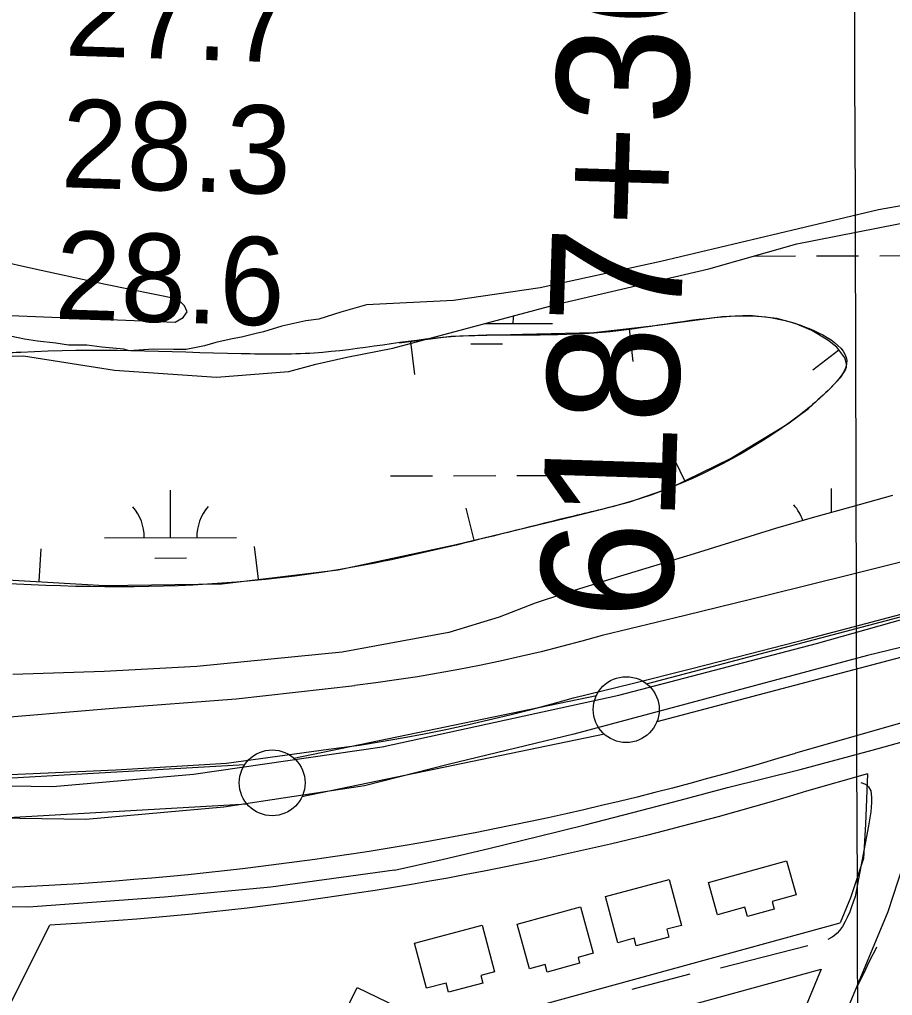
# Model space of a CAD drawing. Extents: x 3361039 to 3398939, y 576572 to 602007.
# Drawn here: x 3385593 to 3386256, y 584866 to 585607 of the extents above; entities that cross this region are included whole.
import ezdxf

# ---------------------------------------------------------------- set-up
doc = ezdxf.new("R2010")
doc.units = 0
for name, color, linetype in [('V-BLDG-OTLN', 7, 'Continuous'), ('V-BORW-LINE', 7, 'Continuous'), ('V-FLOD-BASE', 7, 'Continuous'), ('V-GRID-MAJR', 7, 'Continuous'), ('V-LEVE-TOET', 7, 'Continuous'), ('V-RIVR-RANG', 7, 'Continuous'), ('V-ROAD-CNTR', 7, 'Continuous'), ('V-SITE-VEGE', 7, 'Continuous'), ('V-SURV-IDEN', 7, 'Continuous'), ('V-SURV-LINE', 7, 'Continuous'), ('V-TOPO-MAJR', 7, 'Continuous'), ('V-TOPO-SHOR', 7, 'Continuous'), ('V-WETL-SWMP', 7, 'Continuous')]:
    doc.layers.add(name, color=color, linetype=linetype)

msp = doc.modelspace()

# ---------------------------------------------------------------- linework, layer by layer
at = {"layer": 'V-BLDG-OTLN'}
for points in [[(3386116.51, 584951.84), (3386175.84, 584968.41), (3386183.05, 584942.59), (3386164.78, 584937.48), (3386166.4, 584931.66), (3386146.19, 584926.01), (3386144.21, 584933.11), (3386123.37, 584927.29)], [(3386038.21, 584941.24), (3386086.54, 584954.2), (3386095.91, 584919.25), (3386084.9, 584916.3), (3386086.48, 584910.43), (3386061.7, 584903.79), (3386060.17, 584909.5), (3386047.62, 584906.15)], [(3385971.18, 584920.19), (3386019.31, 584933.36), (3386028.96, 584898.09), (3386017.46, 584894.95), (3386018.64, 584890.64), (3385993.94, 584883.88), (3385992.4, 584889.49), (3385980.48, 584886.23)], [(3385893.26, 584905.87), (3385944.69, 584919.43), (3385954, 584884.08), (3385943.67, 584881.36), (3385945.23, 584875.46), (3385919.06, 584868.56), (3385917.24, 584875.46), (3385902.3, 584871.53)], [(3385826.87, 584825.45), (3385849.68, 584872.18), (3385880.09, 584857.34), (3385874.59, 584846.08), (3385881.6, 584842.67), (3385869.64, 584818.17), (3385863.21, 584821.3), (3385857.85, 584810.33)]]:
    msp.add_lwpolyline(points, close=True, dxfattribs=at)
at = {"layer": 'V-BORW-LINE'}
for p, q in [((3386056.25, 585372.28), (3386059.14, 585347.45)), ((3385890.13, 585362.41), (3385893.34, 585337.62)), ((3386215.54, 585356.09), (3386195.69, 585340.89)), ((3386098.55, 585256.87), (3386087.53, 585279.31)), ((3385938.51, 585211.74), (3385932.63, 585236.04)), ((3385608.44, 585180.3), (3385609.88, 585205.26)), ((3385774.75, 585182.05), (3385771.8, 585206.88))]:
    msp.add_line(p, q, dxfattribs=at)
for points in [[(3385479.9, 585187.69), (3385658.02, 585177.45), (3385747.01, 585178.74), (3385835.24, 585189.26), (3385925.04, 585208.48), (3386014.23, 585230.05), (3386035.51, 585235.28), (3386056.71, 585240.88), (3386088.19, 585251.79), (3386133.12, 585273.84), (3386176.62, 585300.03), (3386192.55, 585311.85), (3386207.38, 585325.51), (3386216.96, 585335.43), (3386220.36, 585340.66), (3386221.23, 585343.19), (3386221.37, 585345.61), (3386219.95, 585350.33), (3386213.89, 585358.25), (3386207.13, 585363.73), (3386194.99, 585370.87), (3386182.35, 585376.31), (3386168.45, 585380.18), (3386147.58, 585382.28), (3386126.76, 585381.36), (3386078.16, 585374.83), (3386029.51, 585369.17), (3385975.3, 585367.99), (3385921.06, 585366.42), (3385881.61, 585361.31)], [(3385594.06, 585354.57), (3385547.09, 585351.02), (3385499.8, 585346.62), (3385437.72, 585344.58), (3385375.62, 585344.42), (3385247.69, 585348.26)]]:
    msp.add_lwpolyline(points, dxfattribs=at)
msp.add_spline([(3382571.75, 585529.85), (3382288.5, 585546.28), (3382119.28, 585556.22), (3382064.39, 585562.69), (3382006.96, 585576.93), (3381796, 585575.03), (3381691.54, 585581.2), (3381638.45, 585584.98), (3381607.38, 585576.47), (3381598.51, 585566.36), (3381610.08, 585526.4), (3381641.99, 585457.34), (3381686.19, 585430.69), (3381748.69, 585412.56), (3381952.89, 585396.92), (3382011.65, 585399.05), (3382060.7, 585404.53), (3382233.38, 585410.22), (3382597.39, 585393.13), (3382822.43, 585377.96), (3382985.12, 585375.03), (3383040.48, 585369.32), (3383111.3, 585349.64), (3383186.01, 585343.18), (3383349.37, 585344.09), (3383670.1, 585328.99), (3383776.96, 585325.83), (3383950.1, 585282.41), (3384048.66, 585281.9), (3384105.28, 585326.49), (3384120.75, 585332.34), (3384160.48, 585298.98), (3384209.82, 585275.27), (3384267.65, 585259.58), (3384373.27, 585255.57), (3384419.94, 585258.58), (3384709.73, 585239.38), (3384826.34, 585210.62), (3384946.51, 585203.35), (3385109.52, 585215.5), (3385207.25, 585213.25), (3385246.28, 585211.98), (3385305.12, 585207.81), (3385479.9, 585187.69), (3385835.24, 585189.26), (3386014.23, 585230.05), (3386056.71, 585240.88), (3386176.62, 585300.03), (3386207.38, 585325.51), (3386221.37, 585345.61), (3386182.35, 585376.31), (3386126.76, 585381.36), (3386029.51, 585369.17), (3385921.06, 585366.42), (3385817.08, 585354.08), (3385761.67, 585353.52), (3385594.41, 585354.59), (3385499.8, 585346.62), (3385375.62, 585344.42), (3385091.32, 585358.84), (3384912.21, 585381.83), (3384861.67, 585385.98), (3384294.69, 585385.71), (3384190.67, 585395.62), (3384128.27, 585377.4), (3384079.07, 585402.54), (3383956.19, 585439.51), (3383615.98, 585443.36), (3383292.93, 585470.42), (3383014.82, 585493.71), (3382867.4, 585507.63), (3382640.11, 585523.01), (3382571.75, 585529.85)], degree=3, dxfattribs=at)
at = {"layer": 'V-FLOD-BASE'}
for points in [[(3385851.46, 585056.16), (3385867.89, 585058.81), (3385884.3, 585061.67), (3385900.66, 585064.74), (3385916.99, 585068.03), (3385933.27, 585071.53), (3385949.51, 585075.24), (3385965.7, 585079.16), (3385981.84, 585083.29), (3385997.92, 585087.62), (3386013.94, 585092.17), (3386058.45, 585103), (3386102.89, 585114.06), (3386147.28, 585125.35), (3386191.62, 585136.87), (3386235.89, 585148.62), (3386506.81, 585220.01)], [(3384347.67, 585099.36), (3384436.64, 585093.72), (3384537.8, 585087.98), (3384639.32, 585081.53), (3384748.75, 585076.82), (3384851.34, 585069.99), (3384975.09, 585060.51), (3385074.47, 585056.23), (3385177.44, 585051.56), (3385286.49, 585043.97), (3385389.43, 585035.72), (3385466.57, 585032.3), (3385569.21, 585033.02), (3385666.5, 585037.36), (3385750.52, 585042.52), (3385828.11, 585053.1), (3385851.46, 585056.16)]]:
    msp.add_lwpolyline(points, dxfattribs=at)
at = {"layer": 'V-GRID-MAJR'}
msp.add_spline([(3386238.02, 582015.2), (3386220.4, 588073.24), (3386202.77, 594134.37), (3386185.13, 600195.51), (3386185.12, 600198.58)], degree=3, dxfattribs=at)
at = {"layer": 'V-LEVE-TOET'}
for points in [[(3386287.96, 585201.41), (3386224.97, 585185.6), (3386161.93, 585169.99), (3386098.84, 585154.57), (3386035.71, 585139.36), (3386020.32, 585135.07), (3386004.88, 585130.98), (3385989.39, 585127.09), (3385973.85, 585123.41), (3385958.26, 585119.94), (3385942.62, 585116.67), (3385926.94, 585113.61), (3385911.23, 585110.76), (3385895.47, 585108.11), (3385879.69, 585105.67), (3385863.87, 585103.44), (3385848.03, 585101.42)], [(3384277.82, 585153.03), (3384414.15, 585145.09), (3384554.88, 585132.69), (3384689.94, 585126.67), (3384819.93, 585119.41), (3384957.48, 585105.76), (3385126.78, 585097.6), (3385249.16, 585091.67), (3385351.25, 585085.24), (3385449.51, 585076.94), (3385561.77, 585075.52), (3385664.59, 585084.32), (3385757.88, 585091.27), (3385848.03, 585101.42)], [(3385878.15, 584961.12), (3385914.41, 584969.37), (3385950.64, 584977.93), (3385986.82, 584986.7), (3386022.95, 584995.68), (3386059.02, 585004.88), (3386095.04, 585014.29), (3386131.01, 585023.91), (3386158.53, 585030.71), (3386186, 585037.71), (3386213.42, 585044.91), (3386240.78, 585052.3), (3386268.1, 585059.89)], [(3385878.15, 584961.12), (3385784.16, 584948.37), (3385703.55, 584940.68), (3385600.1, 584933.16), (3385499.25, 584933.87), (3385340.74, 584943.86), (3385151.77, 584952.17), (3385022.42, 584959.42), (3384849.3, 584965.7), (3384655.92, 584978.48), (3384445.45, 584995.81), (3384273.63, 585007.16)]]:
    msp.add_lwpolyline(points, dxfattribs=at)
at = {"layer": 'V-ROAD-CNTR'}
for points in [[(3386593.92, 585167.42), (3386182.59, 585049.94)], [(3386182.39, 585049.88), (3386169.09, 585045.88), (3386155.81, 585041.97), (3386142.51, 585038.14), (3386129.18, 585034.39), (3386115.83, 585030.71), (3386102.46, 585027.1), (3386089.07, 585023.58), (3386075.66, 585020.13), (3386062.24, 585016.76), (3386048.79, 585013.46), (3386035.32, 585010.24), (3386021.84, 585007.11), (3386008.33, 585004.04), (3385994.81, 585001.06), (3385981.28, 584998.15), (3385967.72, 584995.32), (3385954.15, 584992.57), (3385940.57, 584989.9), (3385926.97, 584987.3), (3385913.35, 584984.78), (3385899.73, 584982.34), (3385886.08, 584979.98), (3385872.43, 584977.7), (3385858.76, 584975.5), (3385845.08, 584973.37), (3385831.38, 584971.32), (3385817.68, 584969.36), (3385803.96, 584967.47), (3385790.23, 584965.66), (3385776.5, 584963.92), (3385762.75, 584962.27), (3385748.99, 584960.7), (3385735.23, 584959.2), (3385721.46, 584957.79), (3385707.67, 584956.45), (3385693.89, 584955.19), (3385680.09, 584954.01), (3385666.29, 584952.91), (3385652.48, 584951.89), (3385638.67, 584950.95), (3385624.85, 584950.09), (3385611.03, 584949.31), (3385597.2, 584948.61), (3385583.36, 584947.98)], [(3386267.59, 585043.02), (3386265.66, 584994.81), (3386263.94, 584964.47), (3386252.56, 584929.67), (3386206.91, 584819.53), (3385971.39, 584365.14)], [(3386237.22, 585034.34), (3386190.83, 585021.09)], [(3386237.22, 585034.34), (3386235.7, 584996.26), (3386234.21, 584970.08), (3386224.4, 584940.09), (3386216.6, 584921.27)], [(3386191.03, 585021.15), (3386177.65, 585017.13), (3386164.2, 585013.17), (3386150.73, 585009.29), (3386137.24, 585005.49), (3386123.72, 585001.76), (3386110.19, 584998.11), (3386096.63, 584994.54), (3386083.05, 584991.05), (3386069.46, 584987.64), (3386055.84, 584984.31), (3386042.21, 584981.05), (3386028.56, 584977.87), (3386014.89, 584974.77), (3386001.2, 584971.75), (3385987.49, 584968.8), (3385973.77, 584965.94), (3385960.03, 584963.15), (3385946.28, 584960.44), (3385932.51, 584957.82), (3385918.72, 584955.27), (3385904.93, 584952.8), (3385891.11, 584950.41), (3385877.29, 584948.1), (3385863.45, 584945.87), (3385849.6, 584943.71), (3385835.73, 584941.64), (3385821.86, 584939.65), (3385807.97, 584937.73), (3385794.07, 584935.9), (3385780.16, 584934.15), (3385766.25, 584932.47), (3385752.32, 584930.88), (3385738.38, 584929.37), (3385724.44, 584927.93), (3385710.49, 584926.58), (3385696.53, 584925.31), (3385682.56, 584924.11), (3385668.59, 584923), (3385654.61, 584921.97), (3385640.62, 584921.02), (3385616.46, 584919.51)], [(3385961.75, 584851.33), (3386216.6, 584921.27)], [(3384904.93, 583480.41), (3385291.76, 584271.23), (3385616.46, 584919.51)], [(3386202.05, 584886.17), (3386179.68, 584832.2), (3385876.77, 584247.77)], [(3385969.69, 584822.4), (3386202.05, 584886.17)]]:
    msp.add_lwpolyline(points, dxfattribs=at)
at = {"layer": 'V-SITE-VEGE'}
msp.add_lwpolyline([(3386315.93, 585474.94), (3386245.63, 585462.63), (3386184.77, 585448.26), (3386080.43, 585423.28), (3385988.77, 585403.31), (3385922.83, 585393.72), (3385856.95, 585390.44), (3385837.38, 585384.99), (3385820.6, 585379.53), (3385810.82, 585378.2), (3385792.65, 585374.14), (3385778.66, 585370.05), (3385773.07, 585368.7), (3385761.89, 585365.98), (3385754.9, 585364.64), (3385742.33, 585361.94), (3385733.93, 585359.2), (3385719.96, 585356.51), (3385710.19, 585356.58), (3385694.84, 585356.69), (3385676.69, 585355.42), (3385672.52, 585356.84), (3385655.78, 585358.35), (3385644.63, 585359.83), (3385630.67, 585359.93), (3385620.92, 585361.39), (3385606.97, 585362.88), (3385597.22, 585364.35), (3385576.31, 585368.68)], dxfattribs=at)
at = {"layer": 'V-SURV-LINE'}
for points in [[(3386069.54, 585102.74), (3387130.14, 585382.68)], [(3387137.8, 585353.67), (3386077.2, 585073.73)], [(3385801.75, 585046.24), (3386031.44, 585093.77)], [(3386037.54, 585064.4), (3385807.85, 585016.87)], [(3385556.51, 585029.43), (3385764.42, 585041.34)], [(3385766.12, 585011.38), (3385558.21, 584999.48)]]:
    msp.add_lwpolyline(points, dxfattribs=at)
for centre in [(3386054.06, 585083.13), (3385785.22, 585027.5)]:
    msp.add_circle(centre, 25, dxfattribs=at)
at = {"layer": 'V-TOPO-MAJR'}
msp.add_lwpolyline([(3384956.25, 585407.96), (3385711.5, 585377.24), (3385717.67, 585380.93), (3385720.61, 585385.01), (3385718.71, 585389.66), (3385713.59, 585394.7), (3385658.79, 585406), (3385604.08, 585417.7), (3385549.49, 585429.98)], dxfattribs=at)
at = {"layer": 'V-TOPO-SHOR'}
for p, q in [((3386125.63, 584887.01), (3386191.88, 584904.14)), ((3386058.67, 584870.81), (3386102.53, 584882.53))]:
    msp.add_line(p, q, dxfattribs=at)
for points in [[(3384949.9, 585056.96), (3385370.77, 585028.55), (3385618.71, 585024.69), (3385725.59, 585034.08), (3385868.83, 585054.95), (3386048.42, 585094.11), (3386198.43, 585133.2), (3386605.27, 585248.05), (3386855.29, 585314.7), (3387037.13, 585358.42), (3387105.31, 585381.36), (3387134.84, 585395.09), (3387162.07, 585417.91), (3387198.4, 585443.03), (3387212.01, 585456.71)], [(3386341.69, 585149.51), (3386237.13, 585124.2), (3386014.38, 585064.45), (3385918.91, 585041.44), (3385855.27, 585025.34), (3385748.41, 585009.12), (3385643.8, 584999.74), (3385509.6, 585001.64), (3385220.69, 585014.49), (3384954.51, 585034.23)], [(3386232.14, 585027.71), (3386235.76, 585026.59), (3386237.92, 585024.57), (3386239.7, 585021.47), (3386240.38, 585016.74), (3386240.16, 585012.57), (3386239.73, 585005.49), (3386237.98, 584994.8), (3386227.83, 584941.35), (3386225.02, 584933.4), (3386223.71, 584929.6), (3386221.86, 584925.26), (3386220.2, 584922.37), (3386218.16, 584918.4), (3386215.95, 584915.51), (3386214.29, 584913.35), (3386212.28, 584911.56), (3386210.45, 584910.31), (3386207.17, 584908.7)], [(3386228.77, 584871.65), (3386234.82, 584883.32), (3386237.11, 584888.79), (3386240.19, 584895.17), (3386243.02, 584900.28), (3386244.44, 584902.98)]]:
    msp.add_lwpolyline(points, dxfattribs=at)
at = {"layer": 'V-WETL-SWMP'}
for p, q in [((3386151.04, 585427.49), (3386182.51, 585427.58)), ((3386198.51, 585427.63), (3386230.51, 585427.71)), ((3386246.51, 585427.76), (3386278.51, 585427.85)), ((3385946.44, 585376.19), (3385998.06, 585376.33)), ((3385948.06, 585376.19), (3385948.06, 585376.62)), ((3385936.11, 585360.73), (3385960.11, 585360.79)), ((3385874.97, 585260.56), (3385906.97, 585260.65)), ((3385922.97, 585260.69), (3385954.97, 585260.78)), ((3385970.97, 585260.82), (3386002.97, 585260.91)), ((3385708.04, 585213.67), (3385707.94, 585249.67)), ((3386209.9, 585232.83), (3386209.85, 585251.05)), ((3385658.04, 585213.53), (3385758.04, 585213.8)), ((3385696.08, 585198.2), (3385720.08, 585198.27))]:
    msp.add_line(p, q, dxfattribs=at)
for points in [[(3384363.39, 585429.51), (3384373.04, 585413.4), (3384402.31, 585408.31), (3384446.98, 585410.09), (3384612.4, 585418.7), (3384759.46, 585395.34), (3384830.51, 585378.79), (3384902.36, 585376.2), (3385069.79, 585372.23), (3385198.06, 585357.38), (3385301.26, 585347.58), (3385396.11, 585341.34), (3385484.77, 585348.39), (3385596.43, 585351.79), (3385665.43, 585340.84), (3385742.84, 585335.42), (3385797.99, 585339.92), (3385818.26, 585345.35), (3385842.02, 585350.77), (3385876.96, 585357.5), (3386002.66, 585391.3), (3386116.87, 585417.75), (3386183.69, 585436.8), (3386274.94, 585454.81)], [(3386256.28, 585245.64), (3386224.66, 585236.89), (3386196.98, 585229.28), (3386167.32, 585220.51), (3386105.63, 585201.42), (3386046.31, 585183.48), (3386007.16, 585171.26), (3385985, 585163.99), (3385957.69, 585153.22), (3385919.33, 585141.78), (3385838.36, 585126.82), (3385728.04, 585115.74), (3385657.55, 585112.04), (3385588.45, 585109.74)]]:
    msp.add_lwpolyline(points, dxfattribs=at)
for centre, start, end in [((3386003.3, 585376.82), 171.37017, 180.93013), ((3385652.8, 585213.99), 359.38648, 40.93014), ((3385763.28, 585214.29), 139.38648, 180.93013), ((3386154.7, 585215.38), 18.66609, 40.93014)]:
    msp.add_arc(centre, 35.25, start, end, dxfattribs=at)

# ---------------------------------------------------------------- texts
at = {"layer": 'V-RIVR-RANG'}
for s, p in [('27.7', (3385627.32, 585579.78)), ('28.3', (3385624.37, 585479.82)), ('28.6', (3385619.58, 585379.93))]:
    msp.add_text(s, height=67, rotation=358.16833, dxfattribs=at).set_placement(p)
at = {"layer": 'V-SURV-IDEN'}
msp.add_text('6187+36.1', height=100, rotation=88.17906, dxfattribs=at).set_placement((3386088.37, 585150.48))

doc.saveas('drawing.dxf')
